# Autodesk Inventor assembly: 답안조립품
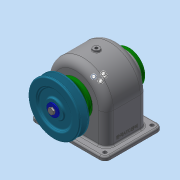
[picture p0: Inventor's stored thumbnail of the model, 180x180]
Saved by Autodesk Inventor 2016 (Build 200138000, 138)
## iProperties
Created: 2022-09
Part Number: 답안조립품
Material: 일반
Document SubType Name: Assembly
Designer: PC-1-10
Author: PC-1-10
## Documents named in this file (16)
- C:\Users\PC-1-10\Desktop\720906V1011\답안조립품.iam
- C:\Users\PC-1-10\Desktop\720906V1011\본체.ipt
- C:\Users\PC-1-10\Desktop\720906V1011\스퍼기어.ipt
- C:\Users\PC-1-10\Desktop\720906V1011\축.ipt
- C:\Users\PC-1-10\Desktop\720906V1011\칼라.ipt
- C:\Users\PC-1-10\Desktop\720906V1011\키 6 x 6 x 22.ipt
- C:\Users\PC-1-10\Desktop\720906V1011\키 5 x 5 x 18.ipt
- C:\Users\PC-1-10\Desktop\720906V1011\뒤커버.ipt
- C:\Users\PC-1-10\Desktop\720906V1011\앞커버.ipt
- C:\Users\PC-1-10\Desktop\720906V1011\베어링 6203.ipt
- C:\Users\PC-1-10\Desktop\720906V1011\볼트 M3 x 10.ipt
- C:\Users\PC-1-10\Desktop\720906V1011\오일 실 17 x 30 x 8.ipt
- C:\Users\PC-1-10\Desktop\720906V1011\V-벨트풀리.ipt
- C:\Users\PC-1-10\Desktop\720906V1011\멈춤나사 M4 x 10.ipt
- C:\Users\PC-1-10\Desktop\720906V1011\와셔 6 x 22.ipt
- C:\Users\PC-1-10\Desktop\720906V1011\육각머리볼트 M3 x 8.ipt
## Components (9 placed, 2 different names)
1. V-벨트풀리:1
2. ISO 4762 M3 x 10:1
3. ISO 4762 M3 x 10:3
4. ISO 4762 M3 x 10:4
5. ISO 4762 M3 x 10:5
6. ISO 4762 M3 x 10:2
7. ISO 4762 M3 x 10:6
8. ISO 4762 M3 x 10:7
9. ISO 4762 M3 x 10:8
